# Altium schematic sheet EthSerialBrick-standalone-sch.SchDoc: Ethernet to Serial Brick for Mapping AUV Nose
size Tabloid; Organization: Monterey Bay Aquarium Research Institute; Address1: 7700 Sandholdt Rd; Address2: Moss Landing, CA 95039-9644; DocumentNumber: 1002305; Revision: 1; SheetNumber: 1; SheetTotal: 1; ApprovedBy: Hans Thomas; CompanyName: MBARI; Engineer: Mark Sibenac
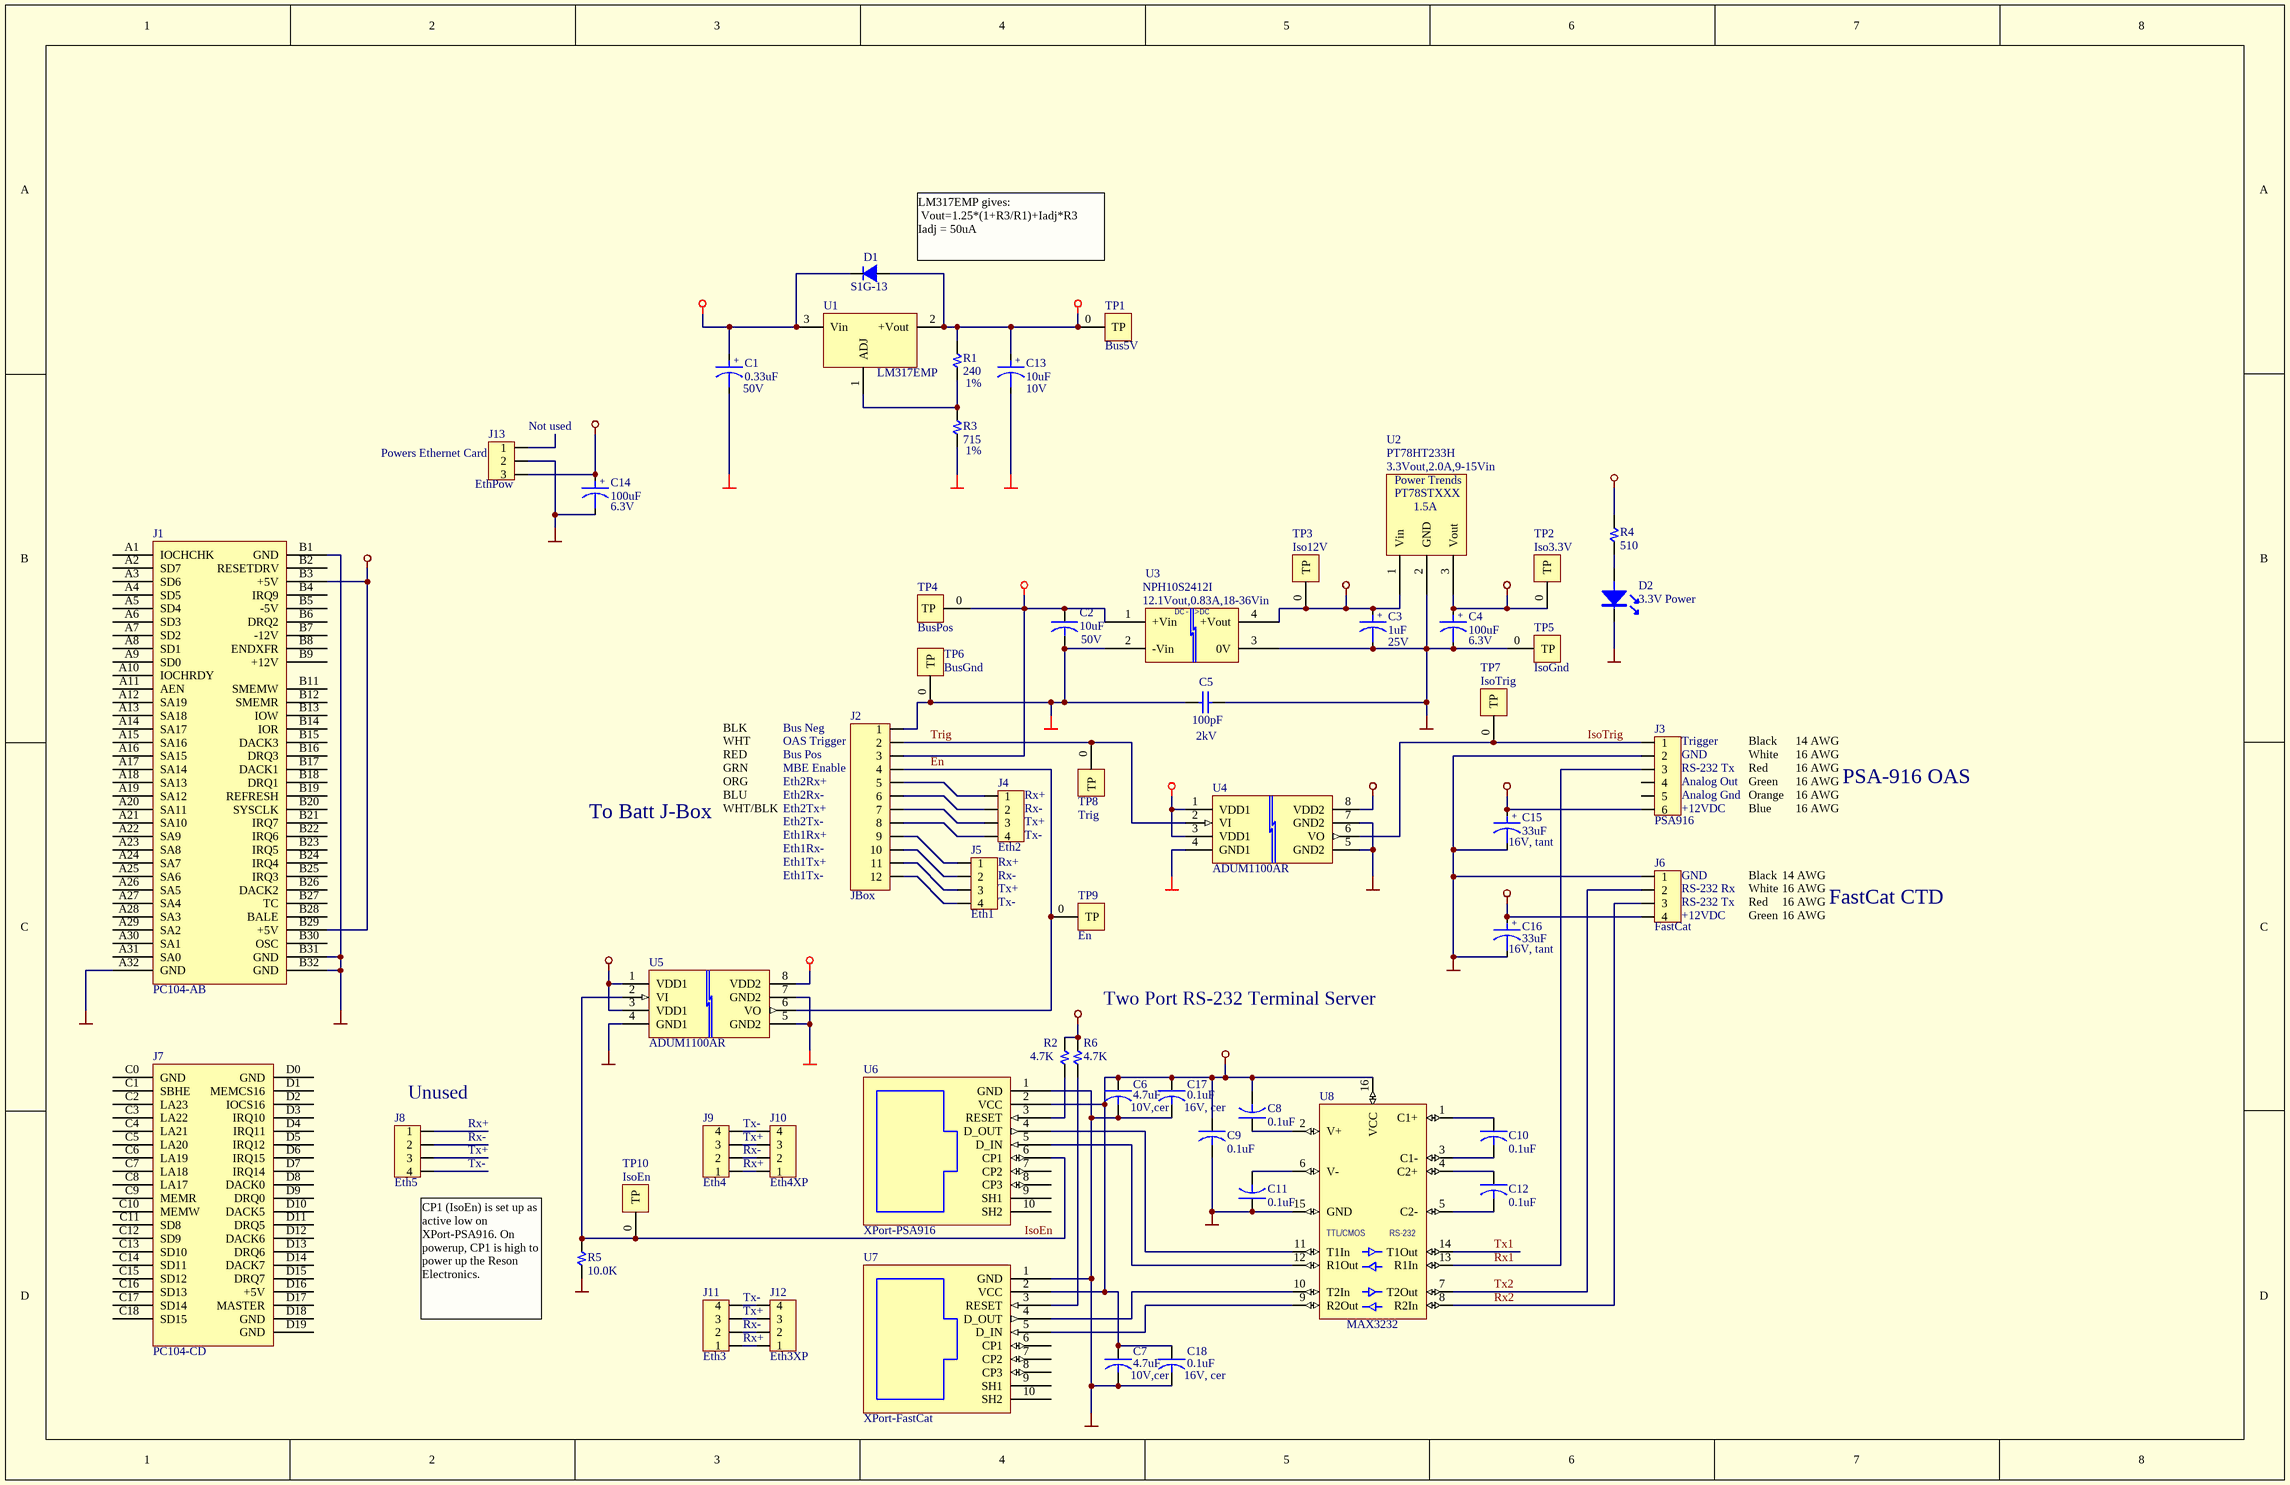
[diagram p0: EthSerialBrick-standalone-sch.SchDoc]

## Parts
C1  0.33uF  DescSheet: 50V  [3528POL]
C2  10uF  DescSheet: 50V  [CAPSTICK-CS4-5]
C3  1uF  DescSheet: 25V  [3216POL]
C4  100uF  DescSheet: 6.3V  [3528POL]
C5  100pF  DescSheet: 2kV  [ECK]
C6  4.7uF  DescSheet: 10V,cer  [1206]
C7  4.7uF  DescSheet: 10V,cer  [1206]
C8  0.1uF  [1206]
C9  0.1uF  [1206]
C10  0.1uF  [1206]
C11  0.1uF  [1206]
C12  0.1uF  [1206]
C13  10uF  DescSheet: 10V  [3216POL]
C14  100uF  DescSheet: 6.3V  [3528POL]
C15  33uF  DescSheet: 16V, tant  [6032POL]
C16  33uF  DescSheet: 16V, tant  [6032POL]
C17  0.1uF  DescSheet: 16V, cer  [1206]
C18  0.1uF  DescSheet: 16V, cer  [1206]
D1  S1G-13  [SMA]
D2  3.3V Power  [SOT-23]
J1  PC104-AB  [PC104-AB]
J2  JBox  [SIP12]
J3  PSA916  [SIP6]
J4  Eth2  [SIP4]
J5  Eth1  [SIP4]
J6  FastCat  [SIP4]
J7  PC104-CD  [PC104-CD]
J8  Eth5  [SIP4]
J9  Eth4  [SIP4]
J10  Eth4XP  [SIP4]
J11  Eth3  [SIP4]
J12  Eth3XP  [SIP4]
J13  EthPow  [SIP3]
R1  240  DescSheet: 1%  [1206]
R2  4.7K  [1206]
R3  715  DescSheet: 1%  [1206]
R4  510  [1206]
R5  10.0K  [1206]
R6  4.7K  [1206]
TP1  Bus5V  [TP-PAD-35]
TP2  Iso3.3V  [TP-PAD-35]
TP3  Iso12V  [TP-PAD-35]
TP4  BusPos  [TP-PAD-35]
TP5  IsoGnd  [TP-PAD-35]
TP6  BusGnd  [TP-PAD-35]
TP7  IsoTrig  [TP-PAD-35]
TP8  Trig  [TP-PAD-35]
TP9  En  [TP-PAD-35]
TP10  IsoEn  [TP-PAD-35]
U1  LM317EMP  [SOT-223]
U2  PT78HT233H  DescSheet: 3.3Vout,2.0A,9-15Vin  [PT78ST-HORIZ]
U3  NPH10S2412I  DescSheet: 12.1Vout,0.83A,18-36Vin  [NPH10S]
U4  ADUM1100AR  [SO-G8/D5]
U5  ADUM1100AR  [SO-G8/D5]
U6  XPort-PSA916  [XPORT]
U7  XPort-FastCat  [XPORT]
U8  MAX3232  [SOIC-16-0.15W]

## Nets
104+5V: J1.B3(+5V) J1.B29(+5V)
104GND: J1.A32(GND) J1.B1(GND) J1.B31(GND) J1.B32(GND)
Bus5V: C13.1 D1.1(K) R1.1 TP1.0(TP) U1.2(+Vout) U1.4(+Vout) U4.1(VDD1) U4.3(VDD1) U5.8(VDD2)
BusGND: C1.2 C2.2 C5.1 C13.2 J2.1 R3.1 TP6.0(TP) U3.2(-Vin) U4.4(GND1) U5.5(GND2) U5.7(GND2)
BusPOS: C1.1 C2.1 D1.2(A) J2.3 TP4.0(TP) U1.3(Vin) U3.1(+Vin)
Iso3.3V: C4.1 C6.1 C7.1 C8.2 C9.1 C14.1 C17.1 C18.1 J13.3 R2.2 R4.1 R6.2 TP2.0(TP) U2.3(Vout) U4.8(VDD2) U5.1(VDD1) U5.3(VDD1) U6.2(VCC) U7.2(VCC) U8.16(VCC)
Iso12V: C3.1 C15.1 C16.1 J3.6 J6.4 TP3.0(TP) U2.1(Vin) U3.4(+Vout)
IsoGND: C3.2 C4.2 C5.2 C6.2 C7.2 C9.2 C11.1 C14.2 C15.2 C16.2 C17.2 C18.2 D2.3(K) J3.2 J6.1 J13.2 R5.1 TP5.0(TP) U2.2(GND) U3.3(0V) U4.5(GND2) U4.7(GND2) U5.4(GND1) U6.1(GND) U7.1(GND) U8.15(GND)
En: J2.4 TP9.0(TP) U5.6(VO)
IsoEn: R5.2 TP10.0(TP) U5.2(VI) U6.6(CP1)
IsoTrig: J3.1 TP7.0(TP) U4.6(VO)
Rx1: J3.3 U8.13(R1In)
Rx2: J6.3 U8.8(R2In)
Trig: J2.2 TP8.0(TP) U4.2(VI)
Tx1: U8.14(T1Out)
Tx2: J6.2 U8.7(T2Out)
NetC8_1: C8.1 U8.2(V+)
NetC10_1: C10.1 U8.1(C1+)
NetC10_2: C10.2 U8.3(C1-)
NetC11_2: C11.2 U8.6(V-)
NetC12_1: C12.1 U8.4(C2+)
NetC12_2: C12.2 U8.5(C2-)
NetD2_2: D2.2(A) R4.2
NetJ2_5: J2.5 J4.1
NetJ2_6: J2.6 J4.2
NetJ2_7: J2.7 J4.3
NetJ2_8: J2.8 J4.4
NetJ2_9: J2.9 J5.1
NetJ2_10: J2.10 J5.2
NetJ2_11: J2.11 J5.3
NetJ2_12: J2.12 J5.4
NetJ9_1: J9.1 J10.1
NetJ9_2: J9.2 J10.2
NetJ9_3: J9.3 J10.3
NetJ9_4: J9.4 J10.4
NetJ11_1: J11.1 J12.1
NetJ11_2: J11.2 J12.2
NetJ11_3: J11.3 J12.3
NetJ11_4: J11.4 J12.4
NetR1_2: R1.2 R3.2 U1.1(ADJ)
NetR2_1: R2.1 U6.3(RESET)
NetR6_1: R6.1 U7.3(RESET)
NetU6_4: U6.4(D_OUT) U8.11(T1In)
NetU6_5: U6.5(D_IN) U8.12(R1Out)
NetU7_4: U7.4(D_OUT) U8.10(T2In)
NetU7_5: U7.5(D_IN) U8.9(R2Out)

Not connected (* = marked no-connect by the designer): J1 A1(IOCHCHK) A2(SD7) A3(SD6) A4(SD5) A5(SD4) A6(SD3) A7(SD2) A8(SD1) A9(SD0) A10(IOCHRDY) A11(AEN) A12(SA19) A13(SA18) A14(SA17) A15(SA16) A16(SA15) A17(SA14) A18(SA13) A19(SA12) A20(SA11) A21(SA10) A22(SA9) A23(SA8) A24(SA7) A25(SA6) A26(SA5) A27(SA4) A28(SA3) A29(SA2) A30(SA1) A31(SA0) B2(RESETDRV) B4(IRQ9) B5(-5V) B6(DRQ2) B7(-12V) B8(ENDXFR) B9(+12V) B10(KEY) B11(SMEMW) B12(SMEMR) B13(IOW) B14(IOR) B15(DACK3) B16(DRQ3) B17(DACK1) B18(DRQ1) B19(REFRESH) B20(SYSCLK) B21(IRQ7) B22(IRQ6) B23(IRQ5) B24(IRQ4) B25(IRQ3) B26(DACK2) B27(TC) B28(BALE) B30(OSC); J3 4 5; J7 C0(GND) C1(SBHE) C2(LA23) C3(LA22) C4(LA21) C5(LA20) C6(LA19) C7(LA18) C8(LA17) C9(MEMR) C10(MEMW) C11(SD8) C12(SD9) C13(SD10) C14(SD11) C15(SD12) C16(SD13) C17(SD14) C18(SD15) C19(KEY) D0(GND) D1(MEMCS16) D2(IOCS16) D3(IRQ10) D4(IRQ11) D5(IRQ12) D6(IRQ15) D7(IRQ14) D8(DACK0) D9(DRQ0) D10(DACK5) D11(DRQ5) D12(DACK6) D13(DRQ6) D14(DACK7) D15(DRQ7) D16(+5V) D17(MASTER) D18(GND) D19(GND); J8 1 2 3 4; J13 1; U6 7(CP2) 8(CP3) 9(SH1) 10(SH2); U7 6(CP1) 7(CP2) 8(CP3) 9(SH1) 10(SH2)

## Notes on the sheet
- LM317EMP gives:
  Vout=1.25*(1+R3/R1)+Iadj*R3
  Iadj = 50uA
- (near J13) Not used
- (near J13) Powers Ethernet Card
- BLK
- WHT
- RED
- (near J2) OAS Trigger
- Bus Neg
- Bus Pos
- (near J3) GND
- (near J3) Trigger
- Black
- White
- 14 AWG
- 16 AWG
- To Batt J-Box
- GRN
- ORG
- BLU
- WHT/BLK
- (near J2) MBE Enable
- Eth1Rx+
- Eth2Tx-
- Eth2Tx+
- Eth2Rx-
- Eth2Rx+
- (near J4) Tx-
- (near J4) Tx+
- (near J4) Rx-
- (near J4) Rx+
- (near J3) RS-232 Tx
- (near J3) +12VDC
- (near J3) Analog Out
- (near J3) Analog Gnd
- Orange
- Blue
- Red
- Green
- PSA-916 OAS
- Eth1Tx-
- Eth1Tx+
- Eth1Rx-
- (near J5) Tx+
- Rx-
- Rx+
- (near J6) GND
- (near J6) RS-232 Rx
- (near J5) Tx-
- (near J6) RS-232 Tx
- (near J6) +12VDC
- FastCat CTD
- Two Port RS-232 Terminal Server
- (near J8) Unused
- (near J8) Tx-
- (near J8) Tx+
- (near J8) Rx-
- (near J8) Rx+
- Tx-
- Tx+
- CP1 (IsoEn) is set up as active low on XPort-PSA916. On powerup, CP1 is high to power up the Reson Electronics.

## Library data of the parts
C1 = CAPACITOR POL: Capacitor; ManufPartNo: T491B334M050AS; Manufacturer: Kemet; VendorPartNo: 399-1659-1-ND; Cost/ea: 0.30; Reference: T041, 773; Vendor: Digi-Key
C2 = CAPACITOR: ManufPartNo: 106K050CS4; Manufacturer: ITW Paktron; Cost/ea: 13.92; Vendor: Future
C3 = CAPACITOR POL: Capacitor; ManufPartNo: T491A105K025AS; Manufacturer: Kemet; VendorPartNo: 399-1624-1-ND; Cost/ea: 0.19; Reference: T041, 773; Vendor: Digi-Key
C4 C14 = CAPACITOR POL: Capacitor; ManufPartNo: T491B107M006AS; Manufacturer: Kemet; VendorPartNo: 399-3195-1-ND; Cost/ea: 0.93; Reference: T041, 772; Vendor: Digi-Key
C5 = Cap: Capacitor; Manufacturer: Panasonic; ManufPartNo: ECK-T3D101KB; VendorPartNo: PCC2092CT-ND; Cost/ea: 0.99; Reference: T041, 813; Vendor: Digi-Key
C6 C7 = CAPACITOR: ManufPartNo: ECJ-3YB1A475K; Manufacturer: Panasonic; VendorPartNo: PCC2295CT-ND; Cost/ea: 0.513; Reference: T041, 822; Vendor: Digi-Key
C8-C12 = CAPACITOR: ManufPartNo: ECJ-3VB1C104K; Manufacturer: Panasonic; VendorPartNo: PCC1870CT-ND; Cost/ea: 0.183; DescSheet: 16V, cer; Reference: T041, 822; Vendor: Digi-Key
C13 = CAPACITOR POL: Capacitor; ManufPartNo: T491A106K010AS; Manufacturer: Panasonic; VendorPartNo: 399-1563-1-ND; Cost/ea: 0.20; Reference: T041, 772; Vendor: Digi-Key
C15 C16 = CAPACITOR POL: Capacitor; ManufPartNo: T491C336K016AS; Manufacturer: Kemet; VendorPartNo: 399-1599-1-ND; Cost/ea: 0.49; Reference: T041, 773; Vendor: Digi-Key
C17 C18 = CAPACITOR: ManufPartNo: ECJ-3VB1C104K; Manufacturer: Panasonic; VendorPartNo: PCC1870CT-ND; Cost/ea: 0.183; Reference: T041, 822; Vendor: Digi-Key
D1 = DIODE_S: Diode; Manufacturer: Diodes Inc; VendorPartNo: S1GDICT-ND; Cost/ea: 0.288; DescSheet: 1A, 400V; Reference: T033, 578; Vendor: Digi-Key
D2 = LED: ManufPartNo: SML-LX15USBC-TR; Manufacturer: Lumex; VendorPartNo: 67-1668-1-ND; Cost/ea: 3.13; DescSheet: Ultra Blue; Reference: T032, 1138; Vendor: Digi-Key
J1 = PC104-AB: PC/104 A&B rails; ManufPartNo: 1185CP-104G; Manufacturer: CommCon
J2 = CON12: Connector 12 pin
J3 = CON6: Connector
J4 J5 J8 J9 J11 = CON4: Connector 4 pin; ManufPartNo: PZC36SAEN; Manufacturer: Sullins; VendorPartNo: S1051-36-ND; Cost/ea: 2.62; Reference: T041, 93; Vendor: Digi-Key
J6 = CON4: Connector
J7 = PC104-CD: PC/104 C&D rails
J10 J12 = CON4: Connector 4 pin
J13 = CON3: Connector; ManufPartNo: PZC36SAEN; Manufacturer: Sullins; VendorPartNo: S1051-36-ND; Cost/ea: 2.62; Reference: T041, 93; Vendor: Digi-Key
R1 = RESISTOR: ManufPartNo: 9C12063A2400FKHFT; Manufacturer: Yaego; VendorPartNo: 311-240FCT-ND; Cost/ea: 0.088; Reference: T041, 861; Vendor: Digi-Key
R2 R6 = RESISTOR: ManufPartNo: 9C12063A4701FKHFT; Manufacturer: Yaego; VendorPartNo: 311-4.70KFCT-ND; Cost/ea: 0.088; Reference: T041, 861; Vendor: Digi-Key
R3 = RESISTOR: ManufPartNo: 9C12063A7150FKHFT; Manufacturer: Yaego; VendorPartNo: 311-715FCT-ND; Cost/ea: 0.088; Reference: T041, 861; Vendor: Digi-Key
R4 = RESISTOR: ManufPartNo: 9C12063A5100FKHFT; Manufacturer: Yageo; VendorPartNo: 311-510FCT-ND; Cost/ea: 0.088; Reference: T041, 861; Vendor: Digi-Key
R5 = RESISTOR: ManufPartNo: 9C12063A1002FKHFT; Manufacturer: Yageo; VendorPartNo: 311-10.0KFCT-ND; Cost/ea: 0.088; Reference: T041, 861; Vendor: Digi-Key
TP1-TP4 = TP PIN: Pad Pin for testpoints; ManufPartNo: 5000; Manufacturer: Keystone; VendorPartNo: 5000K-ND; Cost/ea: 0.023; DescSheet: Red; Reference: T041, 1082; Vendor: Digi-Key
TP5 TP6 = TP PIN: Pad Pin for testpoints; ManufPartNo: 5001; Manufacturer: Keystone; VendorPartNo: 5001K-ND; Cost/ea: 0.023; DescSheet: Black; Reference: T041, 1082; Vendor: Digi-Key
TP7-TP10 = TP PIN: Pad Pin for testpoints; ManufPartNo: 5002; Manufacturer: Keystone; VendorPartNo: 5002K-ND; Cost/ea: 0.023; DescSheet: White; Reference: T041, 1082; Vendor: Digi-Key
U1 = LM317: Regulator; Manufacturer: National Semiconductor; VendorPartNo: LM317EMPCT-ND; Cost/ea: 1.13; DescSheet: 1A; Reference: T041, 457; Vendor: Digi-Key
U2 = PT78STXXX: Power Trends Switching Reg; Manufacturer: TI Powertrends; VendorPartNo: PT78HT233H-ND; Cost/ea: 16.20; Reference: T041, 1170; Vendor: Digi-Key
U3 = NPH10S: DC->DC Isol Converter 10W; Manufacturer: C&D Technologies; VendorPartNo: 580-NPH10S2412I; Cost/ea: 36.18; Reference: pg.1069; Vendor: Mouser
U4 U5 = ADUM1100AR: Digital Isolator; Manufacturer: Analog Devices; Cost/ea: 4.19; Vendor: Arrow Electronics
U6 U7 = XPORT: Serial to Ethernet Converter; Manufacturer: Lantronix
U8 = MAX232: MAX232 Communications Chip; ManufPartNo: MAX3232CSE; Manufacturer: Maxim; VendorPartNo: MAX3232CSE-ND; Cost/ea: 4.19; Reference: T041, 507; Vendor: Digi-Key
